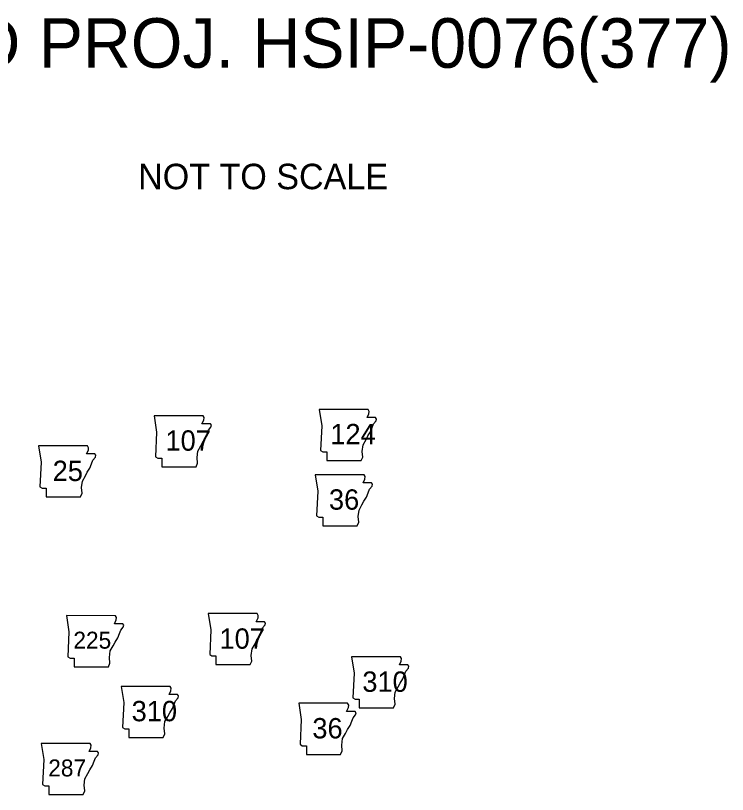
# Model space of a CAD drawing. Extents: x 840176 to 859715, y 1589036 to 1600368.
# Drawn here: x 847690 to 850204, y 1594368 to 1597120 of the extents above; entities that cross this region are included whole.
import ezdxf

# ---------------------------------------------------------------- set-up
doc = ezdxf.new("R2010")
doc.units = 0
doc.layers.add('2', color=7, linetype='Continuous')
doc.layers.add('Default', color=7, linetype='Continuous')

msp = doc.modelspace()

# ---------------------------------------------------------------- linework, layer by layer
at = {"layer": '2'}
for points in [[(848762.4, 1595727.9), (848771.1, 1595670.3), (848767.2, 1595583), (848774.9, 1595578.2), (848789.3, 1595578.2), (848789.3, 1595547.5), (848910.2, 1595547.5), (848916, 1595559.9), (848914.1, 1595580.1), (848916.9, 1595603.1), (848927.5, 1595621.4), (848934.2, 1595634.8), (848943.8, 1595649.2), (848949.6, 1595664.5), (848954.4, 1595677), (848963, 1595687.6), (848964.9, 1595694.3), (848961.1, 1595699.1), (848931.3, 1595699.1), (848938, 1595712.5), (848939, 1595721.2), (848935, 1595727.8)], [(848179.2, 1595705.8), (848187.8, 1595648.2), (848184, 1595560.9), (848191.7, 1595556.1), (848206, 1595556.1), (848206, 1595525.4), (848327, 1595525.4), (848332.7, 1595537.8), (848330.8, 1595558), (848333.7, 1595581), (848344.2, 1595599.3), (848351, 1595612.7), (848360.6, 1595627.1), (848366.3, 1595642.4), (848371.1, 1595654.9), (848379.8, 1595665.5), (848381.7, 1595672.2), (848377.8, 1595677), (848348.1, 1595677), (848354.8, 1595690.4), (848355.8, 1595699.1), (848351.8, 1595705.7)], [(847771.1, 1595599.7), (847779.8, 1595542.2), (847775.9, 1595454.8), (847783.6, 1595450), (847798, 1595450), (847798, 1595419.3), (847918.9, 1595419.3), (847924.7, 1595431.8), (847922.7, 1595451.9), (847925.6, 1595475), (847936.2, 1595493.2), (847942.9, 1595506.6), (847952.5, 1595521), (847958.3, 1595536.4), (847963.1, 1595548.9), (847971.7, 1595559.4), (847973.6, 1595566.1), (847969.8, 1595570.9), (847940, 1595570.9), (847946.7, 1595584.4), (847947.7, 1595593), (847943.7, 1595599.6)], [(848748.2, 1595497.5), (848756.8, 1595439.9), (848753, 1595352.6), (848760.7, 1595347.8), (848775.1, 1595347.8), (848775.1, 1595317.1), (848896, 1595317.1), (848901.7, 1595329.5), (848899.8, 1595349.7), (848902.7, 1595372.7), (848913.2, 1595391), (848920, 1595404.4), (848929.6, 1595418.8), (848935.3, 1595434.1), (848940.1, 1595446.6), (848948.8, 1595457.2), (848950.7, 1595463.9), (848946.8, 1595468.7), (848917.1, 1595468.7), (848923.8, 1595482.1), (848924.8, 1595490.8), (848920.8, 1595497.4)], [(848370.5, 1595007.1), (848379.1, 1594949.5), (848375.3, 1594862.1), (848383, 1594857.3), (848397.4, 1594857.3), (848397.4, 1594826.6), (848518.3, 1594826.6), (848524, 1594839.1), (848522.1, 1594859.3), (848525, 1594882.3), (848535.6, 1594900.5), (848542.3, 1594914), (848551.9, 1594928.4), (848557.6, 1594943.7), (848562.4, 1594956.2), (848571.1, 1594966.8), (848573, 1594973.5), (848569.2, 1594978.3), (848539.4, 1594978.3), (848546.1, 1594991.7), (848547.1, 1595000.3), (848543.1, 1595007)], [(847869.6, 1594999.6), (847878.2, 1594942.1), (847874.4, 1594854.7), (847882, 1594849.9), (847896.4, 1594849.9), (847896.4, 1594819.2), (848017.4, 1594819.2), (848023.1, 1594831.7), (848021.2, 1594851.8), (848024.1, 1594874.9), (848034.6, 1594893.1), (848041.4, 1594906.5), (848051, 1594920.9), (848056.7, 1594936.3), (848061.5, 1594948.8), (848070.1, 1594959.3), (848072.1, 1594966), (848068.2, 1594970.8), (848038.5, 1594970.8), (848045.2, 1594984.3), (848046.2, 1594992.9), (848042.2, 1594999.5)], [(848876.5, 1594854.6), (848885.2, 1594797), (848881.3, 1594709.7), (848889, 1594704.9), (848903.4, 1594704.9), (848903.4, 1594674.2), (849024.3, 1594674.2), (849030.1, 1594686.7), (849028.1, 1594706.8), (849031, 1594729.9), (849041.6, 1594748.1), (849048.3, 1594761.5), (849057.9, 1594775.9), (849063.7, 1594791.3), (849068.5, 1594803.8), (849077.1, 1594814.3), (849079, 1594821), (849075.2, 1594825.8), (849045.4, 1594825.8), (849052.1, 1594839.3), (849053.1, 1594847.9), (849049.1, 1594854.5)], [(848062.9, 1594749.8), (848071.5, 1594692.3), (848067.7, 1594604.9), (848075.3, 1594600.1), (848089.7, 1594600.1), (848089.7, 1594569.4), (848210.7, 1594569.4), (848216.4, 1594581.9), (848214.5, 1594602), (848217.4, 1594625.1), (848227.9, 1594643.3), (848234.7, 1594656.7), (848244.2, 1594671.1), (848250, 1594686.5), (848254.8, 1594699), (848263.4, 1594709.5), (848265.4, 1594716.2), (848261.5, 1594721), (848231.8, 1594721), (848238.5, 1594734.5), (848239.5, 1594743.1), (848235.5, 1594749.8)], [(848690, 1594690), (848698.6, 1594632.4), (848694.8, 1594545.1), (848702.4, 1594540.3), (848716.8, 1594540.3), (848716.8, 1594509.6), (848837.8, 1594509.6), (848843.5, 1594522.1), (848841.6, 1594542.2), (848844.5, 1594565.3), (848855, 1594583.5), (848861.7, 1594596.9), (848871.3, 1594611.3), (848877.1, 1594626.7), (848881.9, 1594639.2), (848890.5, 1594649.7), (848892.5, 1594656.4), (848888.6, 1594661.2), (848858.9, 1594661.2), (848865.6, 1594674.7), (848866.5, 1594683.3), (848862.6, 1594689.9)], [(847780.3, 1594548.5), (847788.9, 1594490.9), (847785.1, 1594403.6), (847792.8, 1594398.8), (847807.2, 1594398.8), (847807.2, 1594368.1), (847928.1, 1594368.1), (847933.8, 1594380.5), (847931.9, 1594400.7), (847934.8, 1594423.7), (847945.3, 1594442), (847952.1, 1594455.4), (847961.7, 1594469.8), (847967.4, 1594485.1), (847972.2, 1594497.6), (847980.9, 1594508.2), (847982.8, 1594514.9), (847978.9, 1594519.7), (847949.2, 1594519.7), (847955.9, 1594533.1), (847956.9, 1594541.8), (847952.9, 1594548.4)]]:
    msp.add_lwpolyline(points, close=True, dxfattribs=at)

# ---------------------------------------------------------------- texts
for s, height, p in [('124', 71.88, (848801.4, 1595605.2)), ('107', 71.88, (848219.1, 1595582.4)), ('25', 71.88, (847820.6, 1595475.2)), ('36', 71.88, (848796.5, 1595374)), ('107', 71.88, (848409.9, 1594882.7)), ('225', 59.9, (847893.8, 1594883)), ('310', 71.88, (848914.5, 1594730.6)), ('310', 71.88, (848099.6, 1594626.5)), ('36', 71.88, (848737.9, 1594566)), ('287', 59.9, (847805, 1594431.6))]:
    msp.add_text(s, height=height, dxfattribs=at).set_placement(p)
at = {"layer": 'Default'}
for s, height, p in [('FED. AID PROJ. HSIP-0076(377)', 175.134, (846717.5, 1596935.2)), ('NOT TO SCALE', 90, (848122.5, 1596506.2))]:
    msp.add_text(s, height=height, dxfattribs=at).set_placement(p)

doc.saveas('drawing.dxf')
